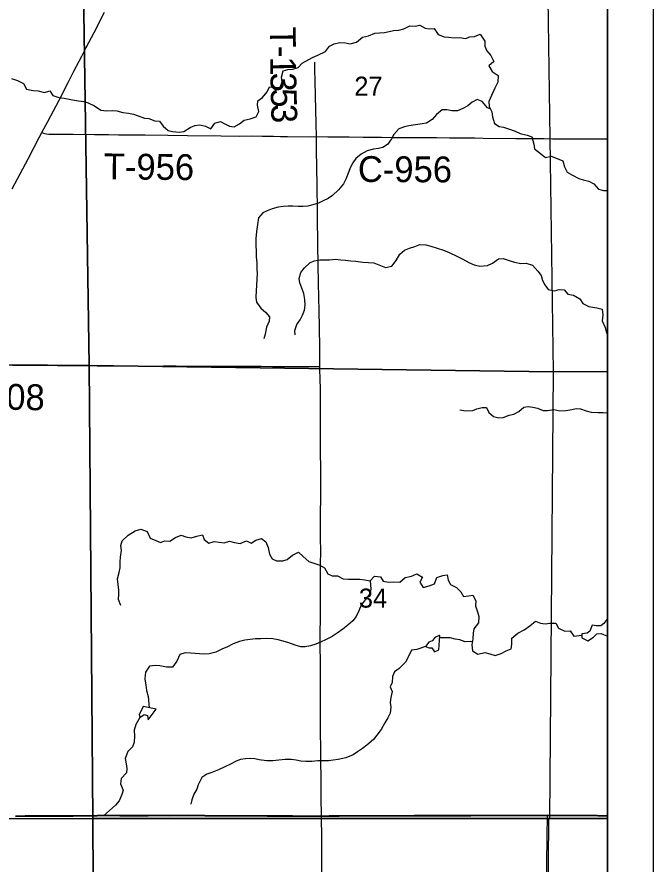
# Model space of a CAD drawing. Extents: x 0 to 70.2, y 0 to 31.4.
# Drawn here: x 7.601 to 9, y 18.211 to 20.074 of the extents above; entities that cross this region are included whole.
import ezdxf

# ---------------------------------------------------------------- set-up
doc = ezdxf.new("R2010")
doc.units = 0
for name, color, linetype in [('GM_X_County_Road', 7, 'Continuous'), ('GM_X_County_Road_Text', 7, 'Continuous'), ('GM_X_Minor_Lake', 7, 'Continuous'), ('GM_X_Minor_River', 7, 'Continuous'), ('GM_X_Section', 7, 'Continuous'), ('GM_X_Section_Text', 7, 'Continuous'), ('GM_X_State_Route', 7, 'Continuous'), ('GM_X_Township_Road', 7, 'Continuous'), ('GM_X_Township_Road_Text', 7, 'Continuous'), ('SH_Cut_Line', 7, 'Continuous'), ('SH_Data', 7, 'Continuous')]:
    doc.layers.add(name, color=color, linetype=linetype)

msp = doc.modelspace()

# ---------------------------------------------------------------- linework, layer by layer
at = {"layer": 'GM_X_County_Road'}
for points in [[(8.2598, 19.8107), (8.2849, 19.8106), (8.3316, 19.8101), (8.3626, 19.8097), (8.403, 19.8095), (8.4279, 19.8092), (8.462, 19.8089), (8.4962, 19.8086), (8.5242, 19.8085), (8.5521, 19.8084), (8.577, 19.8081), (8.6081, 19.8078), (8.6267, 19.8073), (8.6981, 19.8069), (8.7292, 19.8068), (8.7603, 19.8063), (8.7789, 19.8061), (8.8038, 19.8062), (8.8162, 19.8062), (8.8348, 19.8062), (8.8659, 19.8061), (8.8877, 19.8059), (8.9, 19.8056)], [(8.2677, 19.3051), (8.2677, 19.3085), (8.2673, 19.3458), (8.2664, 19.3924), (8.2657, 19.4266), (8.2646, 19.4888), (8.2639, 19.5292), (8.263, 19.5727), (8.2623, 19.6348), (8.2619, 19.6628), (8.2615, 19.6877), (8.2612, 19.7094), (8.2609, 19.7374), (8.26, 19.7872), (8.2598, 19.8107)], [(7.3941, 19.311), (7.403, 19.311), (7.4442, 19.31), (7.4991, 19.3095), (7.5914, 19.3084), (7.6909, 19.3076), (7.7157, 19.3075), (7.7468, 19.3072), (7.7779, 19.3068), (7.8121, 19.3068), (7.868, 19.3063), (7.8928, 19.3063), (7.9239, 19.3068), (7.9394, 19.3066), (7.9518, 19.3064), (8.014, 19.3062), (8.0793, 19.3059), (8.1383, 19.3056), (8.1632, 19.3054), (8.1911, 19.3053), (8.2253, 19.3053), (8.2408, 19.3052), (8.2663, 19.3051), (8.2677, 19.3051)], [(8.271, 18.316), (8.271, 18.3201), (8.2704, 18.3543), (8.2701, 18.3978), (8.2699, 18.4382), (8.2696, 18.4662), (8.269, 18.5004), (8.269, 18.547), (8.2687, 18.6154), (8.2685, 18.6527), (8.2684, 18.6931), (8.2684, 18.7149), (8.2685, 18.7553), (8.2685, 18.7739), (8.2686, 18.8174), (8.269, 18.8703), (8.2693, 18.8983), (8.269, 18.9294), (8.2691, 18.9698), (8.2693, 19.0288), (8.2692, 19.0755), (8.2685, 19.1221), (8.2687, 19.1532), (8.269, 19.1967), (8.2688, 19.2247), (8.2686, 19.2619), (8.2683, 19.2712), (8.2677, 19.3051)], [(8.2719, 18.174), (8.2714, 18.2672), (8.271, 18.316)]]:
    msp.add_lwpolyline(points, dxfattribs=at)
at = {"layer": 'GM_X_Minor_Lake'}
for points in [[(8.9, 18.7499), (8.8982, 18.7489), (8.8918, 18.7398), (8.8853, 18.7352), (8.8751, 18.7352), (8.866, 18.7364), (8.8611, 18.7231), (8.8554, 18.7189), (8.8436, 18.7174), (8.8432, 18.7087), (8.8565, 18.7022), (8.869, 18.7098), (8.8762, 18.717), (8.8857, 18.7178), (8.9, 18.7121)], [(8.5197, 18.7081), (8.5144, 18.702), (8.5072, 18.6986), (8.5, 18.6895), (8.5076, 18.6865), (8.5136, 18.6865), (8.5197, 18.6777), (8.5288, 18.6819), (8.5311, 18.7126)], [(8.5311, 18.7126), (8.5301, 18.7136), (8.529, 18.7136), (8.5281, 18.7131), (8.5268, 18.7125), (8.5231, 18.7109), (8.5197, 18.7081)], [(7.8791, 18.5571), (7.8749, 18.5495), (7.8704, 18.54), (7.8719, 18.5332), (7.8814, 18.5396), (7.8882, 18.5373), (7.8897, 18.5282), (7.9075, 18.5514)], [(7.9075, 18.5514), (7.8791, 18.5571)]]:
    msp.add_lwpolyline(points, dxfattribs=at)
at = {"layer": 'GM_X_Minor_River'}
for points in [[(8.0906, 19.8387), (8.1008, 19.8466), (8.1145, 19.85), (8.127, 19.8546), (8.1335, 19.866), (8.1304, 19.88), (8.1308, 19.8895), (8.1415, 19.8967), (8.1517, 19.9096), (8.157, 19.9206), (8.1699, 19.9191), (8.1798, 19.9191), (8.1843, 19.9316), (8.1828, 19.9418), (8.187, 19.9555), (8.1972, 19.9585), (8.2082, 19.9589), (8.2196, 19.9627), (8.2287, 19.9721), (8.2428, 19.9801), (8.2526, 19.9854), (8.2629, 19.9896), (8.2796, 19.9983), (8.2883, 20.0097), (8.2989, 20.015), (8.311, 20.0176), (8.3236, 20.0172), (8.3342, 20.0146), (8.3482, 20.0187), (8.3615, 20.0293), (8.374, 20.0324), (8.3884, 20.0384), (8.3987, 20.0392), (8.4097, 20.0399), (8.4195, 20.0418), (8.4294, 20.0441), (8.4411, 20.0452), (8.4521, 20.0475), (8.465, 20.0547), (8.4768, 20.0536), (8.487, 20.0562), (8.4988, 20.0494), (8.5083, 20.0479), (8.5185, 20.0486), (8.5272, 20.0353), (8.5405, 20.03), (8.5504, 20.0296), (8.5629, 20.0281), (8.5754, 20.0288), (8.5879, 20.0266), (8.5974, 20.0303), (8.6076, 20.0307), (8.6201, 20.0364), (8.63, 20.0205), (8.63, 20.0098), (8.6342, 19.9992), (8.6436, 19.989), (8.6497, 19.9761), (8.6391, 19.9662), (8.6463, 19.9541), (8.6595, 19.945), (8.6588, 19.9305), (8.6523, 19.9173), (8.6447, 19.9009), (8.639, 19.8877), (8.6394, 19.8767), (8.6458, 19.8653), (8.647, 19.8543), (8.6511, 19.8395), (8.6614, 19.833), (8.6709, 19.8315), (8.6819, 19.8281), (8.6966, 19.8224), (8.708, 19.8178), (8.7232, 19.814), (8.7334, 19.8106), (8.738, 19.7943), (8.7395, 19.784), (8.7524, 19.7738), (8.7637, 19.7647), (8.7763, 19.7681), (8.7892, 19.7624), (8.8013, 19.7574), (8.8054, 19.7445), (8.8111, 19.7324), (8.8229, 19.7263), (8.8369, 19.7187), (8.8464, 19.7161), (8.8585, 19.713), (8.8695, 19.7073), (8.8801, 19.6952), (8.8911, 19.6921), (8.9, 19.6924)], [(7.5893, 19.9384), (7.6025, 19.9342), (7.6158, 19.9277), (7.6226, 19.9152), (7.6367, 19.9122), (7.648, 19.9118), (7.6621, 19.908), (7.6738, 19.9118), (7.6803, 19.9011), (7.6936, 19.8969), (7.7053, 19.895), (7.7235, 19.8916), (7.7364, 19.8897), (7.7485, 19.8878), (7.758, 19.8848), (7.7717, 19.8783), (7.7857, 19.8688), (7.799, 19.8677), (7.8111, 19.868), (7.821, 19.8673), (7.8342, 19.8639), (7.8468, 19.862), (7.8574, 19.8601), (7.868, 19.8563), (7.8816, 19.8513), (7.8915, 19.8505), (7.9048, 19.8452), (7.915, 19.8448), (7.9226, 19.8338), (7.934, 19.8243), (7.9434, 19.8221), (7.9579, 19.8209), (7.9685, 19.822), (7.9821, 19.8308), (7.9928, 19.8349), (8.0034, 19.8364), (8.0159, 19.8338), (8.028, 19.8277), (8.0364, 19.8406), (8.0489, 19.844), (8.0587, 19.8387), (8.069, 19.8338), (8.0788, 19.8322), (8.0906, 19.8387)], [(8.6421, 19.8718), (8.636, 19.8744), (8.6242, 19.8877), (8.6136, 19.8922), (8.6026, 19.8866), (8.5928, 19.8786), (8.5821, 19.8725), (8.57, 19.8676), (8.5579, 19.8676), (8.5465, 19.8699), (8.5366, 19.8695), (8.5241, 19.8593), (8.5142, 19.8487), (8.5017, 19.8407), (8.4922, 19.8392), (8.4774, 19.8366), (8.463, 19.8343), (8.4532, 19.832), (8.441, 19.8278), (8.4304, 19.8157), (8.4247, 19.8062), (8.416, 19.7933), (8.4061, 19.7865), (8.3966, 19.785), (8.3853, 19.7835), (8.3712, 19.7793), (8.3583, 19.7721), (8.3466, 19.7626), (8.3401, 19.7528), (8.334, 19.7418), (8.3287, 19.7285), (8.3245, 19.7175), (8.3192, 19.7069), (8.3082, 19.6936), (8.2953, 19.6815), (8.2855, 19.6747), (8.2748, 19.6694), (8.2646, 19.6644), (8.2521, 19.6606), (8.2407, 19.6576), (8.2297, 19.6569), (8.2195, 19.6572), (8.2077, 19.658), (8.1975, 19.658), (8.1865, 19.6569), (8.1755, 19.6558), (8.1626, 19.6516), (8.1512, 19.6478), (8.1417, 19.6433), (8.1326, 19.6319), (8.1303, 19.6175), (8.1284, 19.6023), (8.1269, 19.5867), (8.1269, 19.5727), (8.1272, 19.5571), (8.1276, 19.5461), (8.1288, 19.5329), (8.1291, 19.5196), (8.1295, 19.5097), (8.1291, 19.4976), (8.1283, 19.4831), (8.1276, 19.4725), (8.1268, 19.4566), (8.1279, 19.4467), (8.1374, 19.4338), (8.1488, 19.4239), (8.1564, 19.4145), (8.1556, 19.405), (8.1499, 19.3917), (8.1469, 19.3765), (8.1442, 19.3659)], [(8.2129, 19.3746), (8.2121, 19.3841), (8.217, 19.3973), (8.2239, 19.4076), (8.2292, 19.4178), (8.2337, 19.4288), (8.2349, 19.4402), (8.2341, 19.4524), (8.2323, 19.4656), (8.2277, 19.4778), (8.2235, 19.4895), (8.2217, 19.499), (8.2258, 19.5123), (8.2334, 19.5225), (8.2452, 19.5332), (8.255, 19.5373), (8.2676, 19.5396), (8.2786, 19.54), (8.2884, 19.54), (8.3021, 19.5411), (8.3134, 19.54), (8.3237, 19.5388), (8.3354, 19.5377), (8.3468, 19.5365), (8.3616, 19.535), (8.3745, 19.5342), (8.3859, 19.5331), (8.4007, 19.527), (8.4117, 19.5228), (8.4257, 19.5258), (8.4352, 19.538), (8.4435, 19.5524), (8.4538, 19.5611), (8.4644, 19.5657), (8.4762, 19.5691), (8.4872, 19.5732), (8.5004, 19.5729), (8.5114, 19.5702), (8.5255, 19.5652), (8.5391, 19.5611), (8.5516, 19.5561), (8.5683, 19.5481), (8.5816, 19.5409), (8.5952, 19.5341), (8.6066, 19.5288), (8.6195, 19.5257), (8.6358, 19.5272), (8.6472, 19.5322), (8.6601, 19.542), (8.6707, 19.5424), (8.6836, 19.5386), (8.6957, 19.5344), (8.709, 19.5317), (8.7208, 19.5321), (8.7352, 19.5283), (8.7469, 19.515), (8.7541, 19.5055), (8.7572, 19.4942), (8.7617, 19.4847), (8.7697, 19.4748), (8.7833, 19.4714), (8.7939, 19.4744), (8.8042, 19.4736), (8.8129, 19.4642), (8.8254, 19.4619), (8.8391, 19.4539), (8.8455, 19.444), (8.8591, 19.4368), (8.8762, 19.4341), (8.8883, 19.4311), (8.8895, 19.4186), (8.8879, 19.4053), (8.8948, 19.3913), (8.8978, 19.3787), (8.9, 19.3783)], [(8.5753, 19.2097), (8.5886, 19.2078), (8.6034, 19.2085), (8.6129, 19.2119), (8.6239, 19.2154), (8.6338, 19.215), (8.6387, 19.204), (8.6493, 19.1952), (8.6607, 19.1926), (8.6705, 19.1929), (8.6834, 19.1979), (8.6937, 19.2001), (8.7047, 19.2062), (8.716, 19.2157), (8.7255, 19.2176), (8.7358, 19.216), (8.7456, 19.2134), (8.7585, 19.2088), (8.768, 19.2084), (8.782, 19.2103), (8.7953, 19.208), (8.8082, 19.2088), (8.8211, 19.2103), (8.831, 19.213), (8.8408, 19.2118), (8.853, 19.2076), (8.8636, 19.2046), (8.8791, 19.2038), (8.8905, 19.2042), (8.9, 19.2035)], [(7.8295, 18.7798), (7.8246, 18.7928), (7.8254, 18.8041), (7.8257, 18.8136), (7.8239, 18.8258), (7.8227, 18.8379), (7.8258, 18.8519), (7.8284, 18.8626), (7.8281, 18.8758), (7.8288, 18.8861), (7.8315, 18.9005), (7.8296, 18.9119), (7.833, 18.9221), (7.8459, 18.9346), (7.8611, 18.9441), (7.8736, 18.9475), (7.8876, 18.9422), (7.8944, 18.9274), (7.907, 18.9229), (7.9168, 18.9183), (7.9267, 18.9221), (7.9377, 18.9209), (7.9502, 18.9293), (7.9627, 18.9342), (7.973, 18.9304), (7.9843, 18.9285), (7.9968, 18.9323), (8.0094, 18.9349), (8.0132, 18.9251), (8.023, 18.9167), (8.0351, 18.9205), (8.0461, 18.919), (8.0571, 18.9171), (8.0689, 18.9209), (8.0795, 18.9178), (8.0924, 18.9159), (8.1064, 18.9216), (8.1163, 18.917), (8.1265, 18.9231), (8.1391, 18.9269), (8.1489, 18.9197), (8.1535, 18.9071), (8.1565, 18.8923), (8.1622, 18.8825), (8.172, 18.8775), (8.1857, 18.8779), (8.1952, 18.8806), (8.2069, 18.8904), (8.2206, 18.8969), (8.2304, 18.8874), (8.243, 18.8764), (8.2562, 18.8718), (8.2672, 18.8684), (8.2775, 18.8623), (8.285, 18.849), (8.2945, 18.8445), (8.3059, 18.8448), (8.3184, 18.8384), (8.3305, 18.8372), (8.3453, 18.8376), (8.3556, 18.8376), (8.3662, 18.8357), (8.3783, 18.8338), (8.3874, 18.8444), (8.4007, 18.8429), (8.4068, 18.833), (8.4185, 18.8311), (8.4303, 18.8315), (8.4432, 18.8307), (8.4549, 18.8409), (8.4686, 18.844), (8.4804, 18.8493), (8.4929, 18.8417), (8.4875, 18.8311), (8.4944, 18.8189), (8.508, 18.8227), (8.5198, 18.8269), (8.5247, 18.8409), (8.5376, 18.8455), (8.5471, 18.847), (8.5494, 18.8352), (8.555, 18.8257), (8.5679, 18.8189), (8.5774, 18.8094), (8.5831, 18.7995), (8.5945, 18.8006), (8.604, 18.8022), (8.61, 18.7896), (8.6096, 18.779), (8.6138, 18.7653), (8.6172, 18.7551), (8.6161, 18.7414), (8.6062, 18.7285), (8.6047, 18.7191), (8.6039, 18.7062), (8.6016, 18.6929), (8.6028, 18.68), (8.6149, 18.6728), (8.6304, 18.6762), (8.6411, 18.6731), (8.6532, 18.6693)], [(8.3783, 18.8338), (8.3798, 18.8156), (8.3772, 18.8049), (8.3669, 18.7917), (8.3582, 18.7803), (8.3529, 18.7682), (8.3472, 18.7556), (8.3396, 18.7462), (8.329, 18.7363), (8.3176, 18.7272), (8.3054, 18.7189), (8.2944, 18.7117), (8.2812, 18.7045), (8.269, 18.6988), (8.2584, 18.6942), (8.2467, 18.6908), (8.2353, 18.6889), (8.2258, 18.6889), (8.2129, 18.692), (8.1989, 18.6973), (8.1867, 18.7015), (8.1754, 18.7041), (8.164, 18.7064), (8.1511, 18.7068), (8.1378, 18.7064), (8.1257, 18.7061), (8.1143, 18.7049), (8.1022, 18.703), (8.0908, 18.7004), (8.0768, 18.6951), (8.0627, 18.6883), (8.0532, 18.6841), (8.0388, 18.6773), (8.024, 18.6731), (8.013, 18.6727), (8.0028, 18.6731), (7.9933, 18.6739), (7.9831, 18.675), (7.9713, 18.6758), (7.9595, 18.6716), (7.9531, 18.6568), (7.9436, 18.6439), (7.93, 18.6439), (7.9155, 18.647), (7.9061, 18.6478), (7.8928, 18.6459), (7.8841, 18.6333), (7.8825, 18.6182), (7.8844, 18.6045), (7.8863, 18.5927), (7.8897, 18.5798), (7.8922, 18.5545)], [(8.6532, 18.6693), (8.6661, 18.6739), (8.6767, 18.6796), (8.6877, 18.6845), (8.6896, 18.6943), (8.6896, 18.708), (8.7025, 18.719), (8.7166, 18.7258), (8.7291, 18.7349), (8.7412, 18.7448), (8.7522, 18.7406), (8.7628, 18.7391), (8.7731, 18.741), (8.786, 18.741), (8.792, 18.73), (8.8057, 18.7235), (8.8178, 18.7239), (8.8258, 18.7121), (8.8435, 18.7141)], [(8.6028, 18.6999), (8.5986, 18.7005), (8.5868, 18.6997), (8.5755, 18.7039), (8.5648, 18.7054), (8.5542, 18.7085), (8.5448, 18.7088), (8.5308, 18.7086)], [(8.5, 18.6895), (8.4806, 18.6827), (8.4689, 18.6816), (8.4624, 18.6672), (8.4556, 18.6546), (8.4419, 18.641), (8.4317, 18.6338), (8.4271, 18.6235), (8.4264, 18.6099), (8.4222, 18.6004), (8.4264, 18.5905), (8.4237, 18.5776), (8.4222, 18.5659), (8.4237, 18.556), (8.4218, 18.5427), (8.4169, 18.5325), (8.4104, 18.5219), (8.402, 18.5071), (8.3926, 18.4946), (8.385, 18.4847), (8.3709, 18.4722), (8.3615, 18.4654), (8.3504, 18.4574), (8.3406, 18.4513), (8.3243, 18.4449), (8.308, 18.4407), (8.2966, 18.4392), (8.2867, 18.4381), (8.2769, 18.4381), (8.2632, 18.4377), (8.2496, 18.4366), (8.2363, 18.4362), (8.2257, 18.4374), (8.215, 18.4396), (8.2044, 18.4408), (8.1908, 18.4412), (8.1775, 18.4393), (8.1638, 18.4381), (8.1502, 18.4378), (8.1339, 18.4404), (8.1244, 18.4423), (8.1149, 18.4431), (8.1039, 18.4427), (8.0929, 18.4408), (8.0831, 18.4371), (8.0709, 18.431), (8.0584, 18.4249), (8.0444, 18.4181), (8.03, 18.4124), (8.0186, 18.409), (8.008, 18.4011), (8, 18.3855), (7.9969, 18.3753), (7.9905, 18.3643), (7.9859, 18.3525), (7.9837, 18.343)], [(7.8719, 18.5332), (7.8631, 18.5176), (7.8593, 18.5055), (7.8597, 18.4922), (7.8593, 18.4789), (7.8552, 18.4687), (7.8453, 18.4588), (7.8392, 18.4429), (7.8415, 18.4311), (7.843, 18.4213), (7.8422, 18.4118), (7.8308, 18.3993), (7.8293, 18.3875), (7.8346, 18.3738), (7.832, 18.3636), (7.8263, 18.3499), (7.8183, 18.3405), (7.805, 18.3287), (7.7917, 18.3173)]]:
    msp.add_lwpolyline(points, dxfattribs=at)
at = {"layer": 'GM_X_Section'}
for points in [[(7.7445, 20.3265), (7.76, 19.3074), (6.7477, 19.3154), (6.7432, 20.333)], [(8.7655, 20.3207), (8.7802, 19.2937), (7.76, 19.3074), (7.7445, 20.3265)], [(6.7477, 19.3154), (7.76, 19.3074), (7.7683, 18.3114), (6.7772, 18.3092), (6.7496, 18.3103)], [(7.76, 19.3074), (8.7802, 19.2937), (8.7726, 18.3113), (8.7699, 18.3113), (7.7683, 18.3114)], [(7.7683, 18.3114), (7.7735, 17.3473), (6.7779, 17.3473), (6.7772, 18.3092)], [(8.7699, 18.3113), (8.763, 17.3339), (7.7735, 17.3473), (7.7683, 18.3114)]]:
    msp.add_lwpolyline(points, close=True, dxfattribs=at)
at = {"layer": 'GM_X_Section_Text'}
for points in [[(7.5981, 18.3162), (7.6197, 18.3167), (7.6383, 18.3169), (7.7251, 18.3173), (7.7779, 18.3181), (7.8059, 18.3179), (7.8277, 18.3176), (7.8494, 18.3175), (7.8899, 18.3181), (7.9179, 18.318), (7.9365, 18.3178), (7.9582, 18.318), (7.9769, 18.3182), (7.9956, 18.318), (8.0142, 18.3176), (8.0391, 18.3173), (8.0577, 18.3172), (8.1012, 18.3174), (8.151, 18.3172), (8.207, 18.3169), (8.2505, 18.3165), (8.2691, 18.3166), (8.2708, 18.3166), (8.2878, 18.3169), (8.3096, 18.3171), (8.3842, 18.3172), (8.4091, 18.3173), (8.4744, 18.3174), (8.5117, 18.3175), (8.5646, 18.3174), (8.5988, 18.3176), (8.6547, 18.3181), (8.7675, 18.3183), (8.8097, 18.3181), (8.8781, 18.3175), (8.9, 18.3173), (8.9, 20.9)], [(8.9, 14.1), (8.9, 18.3173), (8.8781, 18.3175), (8.8097, 18.3181), (8.7675, 18.3183), (8.6547, 18.3181), (8.5988, 18.3176), (8.5646, 18.3174), (8.5117, 18.3175), (8.4744, 18.3174), (8.4091, 18.3173), (8.3842, 18.3172), (8.3096, 18.3171), (8.2878, 18.3169), (8.2708, 18.3166), (8.2691, 18.3166), (8.2505, 18.3165), (8.207, 18.3169), (8.151, 18.3172), (8.1012, 18.3174), (8.0577, 18.3172), (8.0391, 18.3173), (8.0142, 18.3176), (7.9956, 18.318), (7.9769, 18.3182), (7.9582, 18.318), (7.9365, 18.3178), (7.9179, 18.318), (7.8899, 18.3181), (7.8494, 18.3175), (7.8277, 18.3176), (7.8059, 18.3179), (7.7779, 18.3181), (7.7251, 18.3173), (7.6383, 18.3169), (7.6197, 18.3167), (7.5981, 18.3162)]]:
    msp.add_lwpolyline(points, dxfattribs=at)
at = {"layer": 'GM_X_State_Route'}
for points in [[(8.9, 19.2944), (8.9, 20.3216), (8.7655, 20.3207), (8.7802, 19.2937)], [(8.9, 18.3109), (8.9, 19.2944), (8.7802, 19.2937), (8.7726, 18.3113)], [(8.9, 17.3322), (8.9, 18.3109), (8.7726, 18.3113), (8.7699, 18.3113), (8.763, 17.3339)]]:
    msp.add_lwpolyline(points, close=True, dxfattribs=at)
msp.add_lwpolyline([(7.5912, 19.6958), (7.6259, 19.7619), (7.6505, 19.8086), (7.6564, 19.8196), (7.6694, 19.8443), (7.6939, 19.8911), (7.7139, 19.9298), (7.7266, 19.9547), (7.7381, 19.9767), (7.7437, 19.9878), (7.7538, 20.007), (7.771, 20.0401), (7.7937, 20.0844)], dxfattribs=at)
at = {"layer": 'GM_X_Township_Road'}
for points in [[(8.2598, 19.8107), (8.2591, 19.8392), (8.2578, 19.9015), (8.2571, 19.9327), (8.2561, 19.9576), (8.256, 19.9743)], [(7.6564, 19.8196), (7.6595, 19.8181), (7.6625, 19.8174), (7.6664, 19.8168), (7.6715, 19.8163), (7.6817, 19.816), (7.7251, 19.8159), (7.7716, 19.8154), (7.8027, 19.8152), (7.8244, 19.8148), (7.8616, 19.8145), (7.8833, 19.8146), (7.9329, 19.8139), (7.9764, 19.8134), (8.0504, 19.8127), (8.0912, 19.812), (8.1191, 19.8122), (8.1405, 19.8119), (8.1657, 19.8117), (8.1812, 19.8112), (8.1965, 19.8113), (8.2463, 19.8106), (8.2598, 19.8107)], [(8.2677, 19.3051), (8.2677, 19.3085), (8.2673, 19.3458), (8.2664, 19.3924), (8.2657, 19.4266), (8.2646, 19.4888), (8.2639, 19.5292), (8.263, 19.5727), (8.2623, 19.6348), (8.2619, 19.6628), (8.2615, 19.6877), (8.2612, 19.7094), (8.2609, 19.7374), (8.26, 19.7872), (8.2598, 19.8107)], [(8.271, 18.316), (8.271, 18.3201), (8.2704, 18.3543), (8.2701, 18.3978), (8.2699, 18.4382), (8.2696, 18.4662), (8.269, 18.5004), (8.269, 18.547), (8.2687, 18.6154), (8.2685, 18.6527), (8.2684, 18.6931), (8.2684, 18.7149), (8.2685, 18.7553), (8.2685, 18.7739), (8.2686, 18.8174), (8.269, 18.8703), (8.2693, 18.8983), (8.269, 18.9294), (8.2691, 18.9698), (8.2693, 19.0288), (8.2692, 19.0755), (8.2685, 19.1221), (8.2687, 19.1532), (8.269, 19.1967), (8.2688, 19.2247), (8.2686, 19.2619), (8.2683, 19.2712), (8.2677, 19.3051)], [(7.5983, 18.3156), (7.6199, 18.3161), (7.6385, 18.3164), (7.7253, 18.3165), (7.7779, 18.3167), (7.8061, 18.3174), (7.8279, 18.3171), (7.8496, 18.317), (7.8902, 18.3171), (7.9181, 18.3174), (7.9367, 18.3172), (7.9584, 18.3175), (7.9771, 18.3176), (7.9958, 18.3174), (8.0144, 18.3171), (8.0393, 18.3167), (8.0579, 18.3167), (8.1015, 18.3169), (8.1512, 18.3166), (8.2072, 18.3163), (8.2507, 18.316), (8.2694, 18.316), (8.271, 18.316)], [(8.271, 18.316), (8.288, 18.3164), (8.3098, 18.3166), (8.3844, 18.3167), (8.4093, 18.3167), (8.4746, 18.3169), (8.5119, 18.3169), (8.5648, 18.3169), (8.599, 18.317), (8.655, 18.3175), (8.7677, 18.3177)], [(8.2719, 18.174), (8.2714, 18.2672), (8.271, 18.316)], [(8.7664, 18.1651), (8.7668, 18.2116), (8.7675, 18.2707), (8.7677, 18.3177)], [(8.7677, 18.3177), (8.8099, 18.3176), (8.8783, 18.317), (8.9, 18.3167)]]:
    msp.add_lwpolyline(points, dxfattribs=at)
at = {"layer": 'SH_Cut_Line'}
msp.add_lwpolyline([(8.9, 14.1), (8.9, 20.9), (6.7343, 20.9), (6.7395, 20.3365), (6.749, 19.3206), (6.7461, 18.306), (6.7742, 18.3058), (6.7786, 18.1369)], dxfattribs=at)
at = {"layer": 'SH_Data'}
for p, q in [((9, 21), (9, 14)), ((8.9, 20.9), (8.9, 14.1))]:
    msp.add_line(p, q, dxfattribs=at)

# ---------------------------------------------------------------- texts
at = {"layer": 'GM_X_County_Road_Text'}
for s, rotation, p in [('C-956', 359.7293, (8.3509, 19.7111)), ('C-1008', 359.0864, (7.4129, 19.2128))]:
    msp.add_text(s, height=0.05682, rotation=rotation, dxfattribs=at).set_placement(p)
at = {"layer": 'GM_X_Section_Text'}
for s, p in [('27', (8.3431, 19.9007)), ('34', (8.3531, 18.7749))]:
    msp.add_text(s, height=0.04186, rotation=0, dxfattribs=at).set_placement(p)
at = {"layer": 'GM_X_Township_Road_Text'}
for s, height, rotation, p in [('T', 0.0568, 270.4574, (8.1575, 20.0525)), ('-', 0.0568, 270.4574, (8.1579, 20.0101)), ('1', 0.0568, 270.6148, (8.1581, 19.9868)), ('3', 0.0568, 271.4259, (8.1585, 19.9512)), ('5', 0.0568, 271.4512, (8.1593, 19.9165)), ('3', 0.0568, 271.4554, (8.1602, 19.8818)), ('T-956', 0.05682, 359.4438, (7.7922, 19.717))]:
    msp.add_text(s, height=height, rotation=rotation, dxfattribs=at).set_placement(p)

doc.saveas('drawing.dxf')
